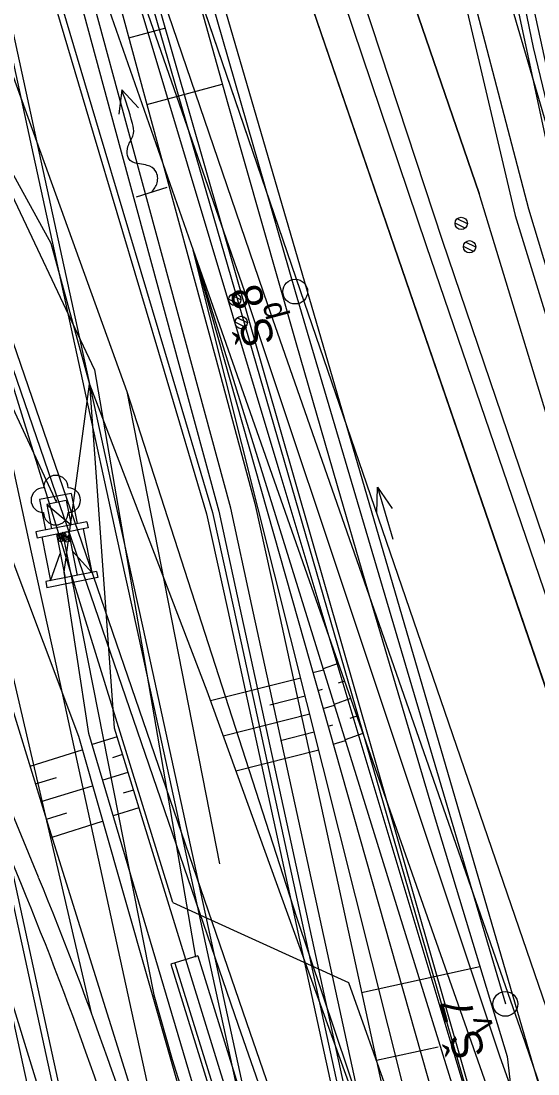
# Model space of a CAD drawing. Extents: x -439815 to -439102, y -1131353 to -1129707.
# Drawn here: x -439580.11 to -439559.22, y -1129992.98 to -1129950.45 of the extents above; entities that cross this region are included whole.
import ezdxf

# ---------------------------------------------------------------- set-up
doc = ezdxf.new("R2010")
doc.units = 0
for name, color, linetype in [('Level 1', 7, 'Continuous'), ('Level 10', 7, 'Continuous'), ('Level 11', 7, 'Continuous'), ('Level 15', 7, 'Continuous'), ('Level 18', 7, 'Continuous'), ('Level 20', 7, 'Continuous'), ('Level 24', 7, 'Continuous'), ('Level 25', 7, 'Continuous'), ('Level 36', 7, 'Continuous'), ('Level 4', 7, 'Continuous'), ('Level 42', 7, 'Continuous'), ('Level 45', 7, 'Continuous'), ('Level 47', 7, 'Continuous'), ('Level 48', 7, 'Continuous'), ('Level 49', 7, 'Continuous'), ('Level 5', 7, 'Continuous'), ('Level 50', 7, 'Continuous'), ('Level 52', 7, 'Continuous'), ('Level 57', 7, 'Continuous'), ('Level 59', 7, 'Continuous'), ('Level 61', 7, 'Continuous'), ('Level 62', 7, 'Continuous'), ('Level 63', 7, 'Continuous'), ('Level 9', 7, 'Continuous')]:
    doc.layers.add(name, color=color, linetype=linetype)

# ---------------------------------------------------------------- blocks, each defined once
blk = doc.blocks.new('LAPAC_')
at = {"layer": 'Level 1'}
for p, q in [((5, 10.49), (5, -10.5)), ((5, 10.49), (7.51, 10.49)), ((7.51, 10.49), (7.53, -10.5)), ((25.5, 10.47), (28, 10.48)), ((25.5, 10.47), (25.5, -10.5)), ((28, 10.48), (28.01, -10.48)), ((-7.5, 6.5), (4.99, 6.51)), ((-7.5, 6.5), (-7.49, -6.51)), ((7.51, 8.5), (25.51, 8.49)), ((25.49, 8.48), (15.5, 2.5)), ((-4.98, 4), (-5, -4)), ((-5, -4), (5, 4)), ((-4.98, 4), (5.01, 4)), ((7.51, 2.5), (25.5, 2.51)), ((-5, -4), (4.99, -4)), ((7.51, 0), (28, 0)), ((7.51, -2.49), (25.5, -2.51)), ((25.51, -8.49), (15.52, -2.5)), ((-7.49, -6.51), (4.99, -6.51)), ((7.51, -8.5), (25.51, -8.49)), ((5, -10.5), (7.53, -10.5)), ((25.5, -10.5), (28.01, -10.48))]:
    blk.add_line(p, q, dxfattribs=at)
for centre in [(8.3, 1.56), (8.3, 0.16), (8.67, -0.69), (9.89, 0.34), (10.54, 1.36), (8.76, -1.44), (9.88, -1.16)]:
    blk.add_circle(centre, 1, dxfattribs=at)

msp = doc.modelspace()

# ---------------------------------------------------------------- linework, layer by layer
at = {"layer": 'Level 10'}
for p, q in [((-439567.29, -1129976.404), (-439567.902, -1129976.618)), ((-439568.312, -1129976.77), (-439567.89, -1129976.65)), ((-439568.806, -1129976.996), (-439572.45, -1129977.912)), ((-439567.04, -1129977.112), (-439567.294, -1129977.2)), ((-439568.622, -1129977.724), (-439570.052, -1129978.084)), ((-439568.106, -1129977.492), (-439567.93, -1129977.44)), ((-439567.902, -1129978.212), (-439567.446, -1129978.084)), ((-439566.79, -1129977.82), (-439567.456, -1129978.052)), ((-439568.44, -1129978.45), (-439571.938, -1129979.33)), ((-439566.542, -1129978.526), (-439566.818, -1129978.624)), ((-439567.698, -1129978.934), (-439567.508, -1129978.88)), ((-439576.226, -1129979.364), (-439577.232, -1129979.674)), ((-439568.258, -1129979.178), (-439569.626, -1129979.522)), ((-439566.294, -1129979.234), (-439567.01, -1129979.486)), ((-439579.738, -1129980.544), (-439577.63, -1129979.894)), ((-439568.074, -1129979.906), (-439571.424, -1129980.748)), ((-439567.494, -1129979.656), (-439567, -1129979.516)), ((-439576.006, -1129980.082), (-439576.41, -1129980.206)), ((-439579.516, -1129981.262), (-439578.678, -1129981.002)), ((-439575.784, -1129980.798), (-439576.806, -1129981.112)), ((-439579.294, -1129981.978), (-439577.218, -1129981.338)), ((-439575.564, -1129981.514), (-439575.974, -1129981.642)), ((-439579.074, -1129982.694), (-439578.25, -1129982.438)), ((-439575.342, -1129982.23), (-439576.378, -1129982.55)), ((-439578.852, -1129983.41), (-439576.81, -1129982.77))]:
    msp.add_line(p, q, dxfattribs=at)
msp.add_lwpolyline([(-439606.718, -1129878.884), (-439599.16, -1129893.286), (-439591.48, -1129910.122), (-439589.662, -1129921.096), (-439588.348, -1129928.69), (-439584.254, -1129940.826), (-439581.56, -1129949.574), (-439575.832, -1129965.416), (-439572.088, -1129984.488)], dxfattribs=at)
at = {"layer": 'Level 11'}
for points in [[(-439631.45, -1129824.71), (-439623.296, -1129852.5), (-439607.812, -1129902.52), (-439594.486, -1129945.364), (-439588.77, -1129963.69), (-439582.318, -1129984.12), (-439576.384, -1130003.39), (-439571.028, -1130020.78), (-439569.524, -1130025.24)], [(-439572.89, -1130002.436), (-439578.954, -1129983.086), (-439585.23, -1129962.72)]]:
    msp.add_lwpolyline(points, dxfattribs=at)
at = {"layer": 'Level 15'}
for p, q in [((-439575.752, -1129951.124), (-439574.25, -1129950.717)), ((-439575.021, -1129953.819), (-439571.975, -1129952.994)), ((-439562.158, -1129958.81), (-439562.568, -1129958.608)), ((-439562.072, -1129958.642), (-439562.488, -1129958.44)), ((-439561.736, -1129959.588), (-439562.152, -1129959.384)), ((-439561.82, -1129959.754), (-439562.232, -1129959.554)), ((-439571.222, -1129961.716), (-439571.638, -1129961.514)), ((-439571.308, -1129961.884), (-439571.718, -1129961.682)), ((-439570.96, -1129962.646), (-439571.376, -1129962.444)), ((-439571.044, -1129962.814), (-439571.456, -1129962.612)), ((-439566.346, -1129989.687), (-439561.562, -1129988.644)), ((-439565.749, -1129992.426), (-439563.249, -1129991.881))]:
    msp.add_line(p, q, dxfattribs=at)
for centre in [(-439562.319, -1129958.622), (-439561.982, -1129959.566), (-439571.47, -1129961.695), (-439571.207, -1129962.626)]:
    msp.add_circle(centre, 0.25, dxfattribs=at)
at = {"layer": 'Level 18'}
msp.add_lwpolyline([(-439631.86, -1129744.036), (-439633.367, -1129748.063), (-439622.927, -1129795.938), (-439612.487, -1129843.813), (-439602.046, -1129891.688), (-439593.233, -1129932.103), (-439588.758, -1129952.621), (-439584.284, -1129973.139), (-439579.81, -1129993.657), (-439575.335, -1130014.174), (-439566.386, -1130055.21)], dxfattribs=at)
at = {"layer": 'Level 20'}
for points in [[(-439447.35, -1130302.89), (-439457.16, -1130275.562), (-439478.968, -1130210.544), (-439490.24, -1130177.636), (-439501.606, -1130144.528), (-439511.068, -1130116.958), (-439519.726, -1130091.71), (-439522.682, -1130083.14), (-439529.956, -1130061.912), (-439534.024, -1130050.036), (-439543.72, -1130021.718), (-439554.45, -1129990.362), (-439564.874, -1129960.014), (-439575.322, -1129929.52)], [(-439450.914, -1130305.246), (-439460.972, -1130277.082), (-439482.918, -1130211.888), (-439494.254, -1130178.768), (-439505.592, -1130145.672), (-439514.996, -1130118.198), (-439526.684, -1130084.16), (-439534.114, -1130062.498), (-439537.924, -1130051.384), (-439547.688, -1130022.904), (-439558.398, -1129991.686), (-439568.82, -1129961.348), (-439579.29, -1129930.716)]]:
    msp.add_lwpolyline(points, dxfattribs=at)
at = {"layer": 'Level 24'}
msp.add_line((-439580.77, -1129965.363), (-439578.671, -1129969.901), dxfattribs=at)
at = {"layer": 'Level 36'}
for p, q in [((-439573.97, -1129986.06), (-439607.88, -1129876.57)), ((-439573.27, -1129886.24), (-439556.9, -1129961.42)), ((-439573.97, -1129986.06), (-439572.59, -1129986.69)), ((-439572.59, -1129986.69), (-439566.87, -1129989.29)), ((-439566.87, -1129989.29), (-439527.69, -1130099.7))]:
    msp.add_line(p, q, dxfattribs=at)
at = {"layer": 'Level 4'}
for points in [[(-439452.672, -1130307.618), (-439463.136, -1130278.208), (-439473.444, -1130247.422), (-439485.028, -1130212.568), (-439496.122, -1130179.246), (-439507.47, -1130146.338), (-439516.97, -1130118.814), (-439528.894, -1130083.662), (-439539.69, -1130052.08), (-439549.11, -1130024.836), (-439560.748, -1129992.304), (-439571.06, -1129961.386), (-439580.88, -1129933.18), (-439592.05, -1129899.854), (-439602.118, -1129867.674), (-439610.398, -1129839.158), (-439617.774, -1129811.206), (-439624.664, -1129780.682), (-439629.998, -1129755.268)], [(-439452.072, -1130307.172), (-439462.466, -1130278.094), (-439473.084, -1130245.544), (-439484.196, -1130212.422), (-439495.494, -1130179.146), (-439506.764, -1130146.202), (-439516.426, -1130118.702), (-439528.244, -1130083.58), (-439539.098, -1130051.84), (-439548.434, -1130024.652), (-439559.722, -1129991.734), (-439570.14, -1129961.918), (-439579.974, -1129933.094), (-439590.708, -1129900.372), (-439601.098, -1129867.326), (-439609.248, -1129839.62), (-439616.746, -1129811.082), (-439623.958, -1129780.222), (-439629.3, -1129755.206)], [(-439446.102, -1130302.732), (-439455.792, -1130275.852), (-439466.676, -1130243.236), (-439477.16, -1130212.046), (-439488.92, -1130177.274), (-439500.288, -1130144.12), (-439509.364, -1130116.456), (-439521.914, -1130080.954), (-439532.724, -1130049.53), (-439541.918, -1130022.91), (-439553.308, -1129989.992), (-439563.72, -1129959.534), (-439573.732, -1129929.866), (-439583.77, -1129899.796), (-439594.604, -1129865.112), (-439602.866, -1129836.696), (-439610.248, -1129808.686), (-439617.812, -1129776.402), (-439620.902, -1129760.638), (-439620.878, -1129760.216)], [(-439445.336, -1130302.16), (-439455.084, -1130275.71), (-439466.188, -1130243.062), (-439488.304, -1130177.006), (-439499.622, -1130143.812), (-439508.924, -1130116.27), (-439521.236, -1130080.8), (-439532.228, -1130049.328), (-439540.848, -1130022.744), (-439552.746, -1129989.722), (-439563.07, -1129959.314), (-439572.718, -1129930.014), (-439582.84, -1129899.55), (-439593.798, -1129865.15), (-439602.014, -1129836.3), (-439609.444, -1129808.656), (-439617.162, -1129776.376), (-439620.256, -1129761.088), (-439620.404, -1129760.148)]]:
    msp.add_lwpolyline(points, dxfattribs=at)
at = {"layer": 'Level 42'}
for points in [[(-439571.26, -1129941.374), (-439564.874, -1129960.014), (-439554.45, -1129990.362), (-439543.72, -1130021.718), (-439534.024, -1130050.036), (-439529.956, -1130061.912), (-439522.682, -1130083.14), (-439519.726, -1130091.71), (-439511.068, -1130116.958), (-439501.606, -1130144.528), (-439490.24, -1130177.636), (-439478.968, -1130210.544), (-439457.16, -1130275.562), (-439447.35, -1130302.89), (-439445.462, -1130308.388), (-439445.064, -1130309.558), (-439434.464, -1130340.548), (-439423.826, -1130371.538), (-439413.424, -1130401.962), (-439403.314, -1130431.488), (-439395.105, -1130455.427)], [(-439399.158, -1130456.267), (-439407.226, -1130432.678), (-439417.232, -1130403.478), (-439427.682, -1130373.028), (-439438.464, -1130341.588), (-439448.942, -1130311.012), (-439450.914, -1130305.246), (-439460.972, -1130277.082), (-439482.918, -1130211.888), (-439494.254, -1130178.768), (-439505.592, -1130145.672), (-439514.996, -1130118.198), (-439526.684, -1130084.16), (-439534.114, -1130062.498), (-439537.924, -1130051.384), (-439547.688, -1130022.904), (-439558.398, -1129991.686), (-439568.82, -1129961.348), (-439575.094, -1129942.992)]]:
    msp.add_lwpolyline(points, dxfattribs=at)
at = {"layer": 'Level 45'}
msp.add_lwpolyline([(-439543.649, -1130001.679), (-439556.991, -1129961.508), (-439559.4, -1129951.517), (-439562.492, -1129936.521)], dxfattribs=at)
at = {"layer": 'Level 47'}
for p, q in [((-439577.344, -1129932.554), (-439569.026, -1129961.378)), ((-439569.026, -1129961.378), (-439560.537, -1129990.152))]:
    msp.add_line(p, q, dxfattribs=at)
for centre in [(-439569.026, -1129961.378), (-439560.537, -1129990.152)]:
    msp.add_circle(centre, 0.5, dxfattribs=at)
at = {"layer": 'Level 48'}
for p, q in [((-439576.032, -1129953.234), (-439576.158, -1129954.215)), ((-439576.032, -1129953.234), (-439575.363, -1129953.959)), ((-439574.215, -1129957.17), (-439575.456, -1129957.563))]:
    msp.add_line(p, q, dxfattribs=at)
msp.add_spline([(-439574.837, -1129957.371), (-439574.606, -1129956.979), (-439574.665, -1129956.52), (-439575.005, -1129956.278), (-439575.324, -1129956.22), (-439575.696, -1129956.082), (-439575.816, -1129955.803), (-439575.756, -1129955.432), (-439575.561, -1129954.993), (-439575.603, -1129954.592), (-439576.032, -1129953.234)], degree=3, dxfattribs=at)
at = {"layer": 'Level 49'}
msp.add_line((-439565.704, -1129969.274), (-439565.081, -1129971.38), dxfattribs=at)
msp.add_lwpolyline([(-439565.732, -1129970.325), (-439565.704, -1129969.274), (-439565.109, -1129970.141)], dxfattribs=at)
at = {"layer": 'Level 5'}
for points in [[(-439524.128, -1130104.684), (-439542.36, -1130053.899), (-439560.483, -1129998.857), (-439575.708, -1129945.714), (-439590.289, -1129890.237), (-439603.222, -1129834.191), (-439614.978, -1129781.165), (-439626.657, -1129727.981), (-439631.05, -1129707.012)], [(-439587.117, -1129895.735), (-439584.686, -1129905.44), (-439582.203, -1129915.134), (-439580.689, -1129920.945), (-439579.669, -1129924.816), (-439577.082, -1129934.487), (-439574.443, -1129944.147), (-439571.752, -1129953.795), (-439569.009, -1129963.432), (-439567.338, -1129969.208), (-439566.214, -1129973.057), (-439563.366, -1129982.671), (-439560.466, -1129992.274), (-439559.308, -1130002.256), (-439558.201, -1130012.25), (-439555.572, -1130021.911), (-439553.075, -1130031.602), (-439552.175, -1130035.027)], [(-439590.756, -1129896.529), (-439588.625, -1129906.299), (-439586.494, -1129916.07), (-439585.216, -1129921.932), (-439584.168, -1129925.797), (-439581.549, -1129935.461), (-439578.93, -1129945.125), (-439576.311, -1129954.789), (-439573.692, -1129964.453), (-439572.12, -1129970.251), (-439571.268, -1129974.159), (-439569.137, -1129983.93), (-439567.006, -1129993.7), (-439564.876, -1130003.47), (-439562.745, -1130013.241), (-439560.614, -1130023.011), (-439558.484, -1130032.781), (-439556.976, -1130039.694), (-439556.353, -1130042.552), (-439554.222, -1130052.322), (-439552.092, -1130062.093), (-439551.741, -1130063.699)], [(-439556.38, -1130040.02), (-439557.995, -1130032.675), (-439560.126, -1130022.905), (-439562.257, -1130013.134), (-439564.387, -1130003.364), (-439566.518, -1129993.593), (-439568.649, -1129983.823), (-439570.779, -1129974.053), (-439571.634, -1129970.132), (-439573.209, -1129964.322), (-439575.828, -1129954.658), (-439578.447, -1129944.994), (-439581.067, -1129935.33), (-439583.686, -1129925.667), (-439584.73, -1129921.813), (-439586.006, -1129915.963), (-439588.136, -1129906.193), (-439590.267, -1129896.422)], [(-439589.29, -1129896.209), (-439587.159, -1129905.98), (-439585.029, -1129915.75), (-439583.75, -1129921.612), (-439582.703, -1129925.478), (-439580.084, -1129935.142), (-439577.464, -1129944.805), (-439574.845, -1129954.469), (-439572.226, -1129964.133), (-439570.654, -1129969.931), (-439569.802, -1129973.84), (-439567.672, -1129983.61), (-439565.541, -1129993.38), (-439563.41, -1130003.151), (-439561.28, -1130012.921), (-439559.149, -1130022.691), (-439557.018, -1130032.462), (-439555.511, -1130039.375), (-439554.888, -1130042.232), (-439552.757, -1130052.003), (-439550.626, -1130061.773), (-439548.496, -1130071.543), (-439547.692, -1130075.226)], [(-439592.465, -1129896.902), (-439590.335, -1129906.672), (-439588.204, -1129916.442), (-439586.926, -1129922.305), (-439586.073, -1129926.213), (-439583.943, -1129935.983), (-439581.812, -1129945.754), (-439579.682, -1129955.524), (-439577.551, -1129965.294), (-439576.272, -1129971.157), (-439575.42, -1129975.065), (-439573.29, -1129984.835), (-439571.159, -1129994.605), (-439569.028, -1130004.376), (-439566.898, -1130014.146), (-439564.767, -1130023.917), (-439562.636, -1130033.687), (-439561.129, -1130040.6)], [(-439592.221, -1129896.848), (-439590.091, -1129906.619), (-439587.96, -1129916.389), (-439586.682, -1129922.251), (-439585.829, -1129926.16), (-439583.699, -1129935.93), (-439581.568, -1129945.7), (-439579.437, -1129955.471), (-439577.307, -1129965.241), (-439576.028, -1129971.103), (-439575.176, -1129975.011), (-439573.045, -1129984.782), (-439570.915, -1129994.552), (-439568.784, -1130004.323), (-439566.653, -1130014.093), (-439564.523, -1130023.863), (-439562.392, -1130033.634), (-439560.884, -1130040.547)], [(-439595.885, -1129897.647), (-439593.754, -1129907.418), (-439591.624, -1129917.188), (-439590.345, -1129923.05), (-439589.493, -1129926.959), (-439587.362, -1129936.729), (-439585.232, -1129946.499), (-439583.101, -1129956.27), (-439580.97, -1129966.04), (-439579.692, -1129971.902), (-439578.84, -1129975.81), (-439576.709, -1129985.581), (-439574.578, -1129995.351), (-439572.448, -1130005.122), (-439570.317, -1130014.892), (-439568.186, -1130024.662), (-439566.056, -1130034.433), (-439564.548, -1130041.346)], [(-439599.549, -1129898.446), (-439597.418, -1129908.217), (-439595.288, -1129917.987), (-439594.009, -1129923.849), (-439593.157, -1129927.758), (-439591.026, -1129937.528), (-439588.896, -1129947.298), (-439586.765, -1129957.069), (-439584.634, -1129966.839), (-439583.356, -1129972.701), (-439582.504, -1129976.609), (-439580.373, -1129986.38), (-439578.242, -1129996.15), (-439576.112, -1130005.921), (-439573.981, -1130015.691), (-439571.85, -1130025.461), (-439569.72, -1130035.232), (-439568.212, -1130042.145)], [(-439599.305, -1129898.393), (-439597.174, -1129908.164), (-439595.043, -1129917.934), (-439593.765, -1129923.796), (-439592.913, -1129927.704), (-439590.782, -1129937.475), (-439588.651, -1129947.245), (-439586.521, -1129957.015), (-439584.39, -1129966.786), (-439583.112, -1129972.648), (-439582.259, -1129976.556), (-439580.129, -1129986.327), (-439577.998, -1129996.097), (-439575.867, -1130005.867), (-439573.737, -1130015.638), (-439571.606, -1130025.408), (-439569.475, -1130035.178), (-439567.968, -1130042.091)], [(-439587.96, -1129916.389), (-439586.682, -1129922.251), (-439585.536, -1129926.096), (-439582.673, -1129935.706), (-439579.809, -1129945.317), (-439576.946, -1129954.927), (-439574.082, -1129964.538), (-439572.364, -1129970.304), (-439571.512, -1129974.212), (-439569.381, -1129983.983), (-439567.251, -1129993.753), (-439565.12, -1130003.524), (-439562.989, -1130013.294), (-439560.859, -1130023.064), (-439558.728, -1130032.835), (-439557.22, -1130039.748), (-439556.597, -1130042.605), (-439554.467, -1130052.375), (-439552.336, -1130062.146), (-439550.379, -1130071.121)], [(-439586.934, -1129922.311), (-439586.926, -1129922.305), (-439585.78, -1129926.149), (-439582.917, -1129935.76), (-439580.053, -1129945.37), (-439577.19, -1129954.981), (-439574.327, -1129964.591), (-439572.609, -1129970.358), (-439571.756, -1129974.266), (-439569.626, -1129984.036), (-439567.495, -1129993.806), (-439565.364, -1130003.577), (-439563.234, -1130013.347), (-439561.103, -1130023.118), (-439558.972, -1130032.888), (-439557.465, -1130039.801), (-439556.842, -1130042.658), (-439554.711, -1130052.429), (-439552.58, -1130062.199), (-439551.985, -1130064.928)]]:
    msp.add_lwpolyline(points, dxfattribs=at)
at = {"layer": 'Level 50'}
msp.add_line((-439578.732, -1129969.804), (-439578.66, -1129969.804), dxfattribs=at)
for centre, start, end in [((-439578.701, -1129969.303), 0, 180), ((-439579.201, -1129969.803), 90, 270), ((-439578.201, -1129969.803), 270, 90), ((-439578.701, -1129970.303), 180, 0)]:
    msp.add_arc(centre, 0.5, start, end, dxfattribs=at)
at = {"layer": 'Level 52'}
for p, q in [((-439583.644, -1129950.788), (-439577.136, -1129964.538)), ((-439577.136, -1129964.538), (-439573.056, -1129988.268)), ((-439582.952, -1129966.168), (-439577.266, -1129990.506)), ((-439579.398, -1129985.038), (-439584.406, -1129972.9)), ((-439580.09, -1129985.324), (-439585.118, -1129973.142)), ((-439578.032, -1129973.138), (-439574.742, -1129989.788)), ((-439572.956, -1129988.212), (-439574.054, -1129988.552))]:
    msp.add_line(p, q, dxfattribs=at)
for points in [[(-439572.956, -1129988.212), (-439566.758, -1130008.234)], [(-439574.054, -1129988.552), (-439567.864, -1130008.55)], [(-439573.89, -1129988.502), (-439570.934, -1129998.056)], [(-439574.742, -1129989.788), (-439574, -1129992.396), (-439568.824, -1130008.828)]]:
    msp.add_lwpolyline(points, dxfattribs=at)
for radius in [150.5, 151.25]:
    msp.add_arc((-439719.223, -1130042.705), radius, 16.09885, 22.41188, dxfattribs=at)
at = {"layer": 'Level 57'}
for p, q in [((-439615.997, -1129861.04), (-439571.326, -1129991.012)), ((-439571.326, -1129991.012), (-439532.649, -1130102.737))]:
    msp.add_line(p, q, dxfattribs=at)
at = {"layer": 'Level 59'}
for p, q in [((-439615.666, -1129860.926), (-439570.995, -1129990.899)), ((-439570.995, -1129990.898), (-439532.318, -1130102.623))]:
    msp.add_line(p, q, dxfattribs=at)
msp.add_lwpolyline([(-439565.323, -1129925.255), (-439558.917, -1129955.176), (-439557.476, -1129961.905), (-439549.066, -1129985.001)], dxfattribs=at)
at = {"layer": 'Level 61'}
for p, q in [((-439547.146, -1129994.737), (-439562.474, -1129942.35)), ((-439573.227, -1129945.323), (-439557.81, -1129998.142))]:
    msp.add_line(p, q, dxfattribs=at)
at = {"layer": 'Level 62'}
msp.add_line((-439560.603, -1129998.786), (-439575.875, -1129946.07), dxfattribs=at)
at = {"layer": 'Level 63'}
msp.add_lwpolyline([(-439559.899, -1130001.173), (-439569.713, -1129968.453), (-439577.958, -1129940.931), (-439581.389, -1129927.721), (-439587.866, -1129899.446), (-439590.167, -1129890.323), (-439596.266, -1129862.915), (-439602.978, -1129834.556), (-439615.089, -1129778.896), (-439619.056, -1129758.708), (-439624.106, -1129738.276), (-439628.163, -1129719.403), (-439630.545, -1129707.012)], dxfattribs=at)
at = {"layer": 'Level 9'}
for p, q in [((-439573.156, -1129959.7), (-439550.138, -1130025.226)), ((-439578.362, -1129972.718), (-439577.34, -1129965.12))]:
    msp.add_line(p, q, dxfattribs=at)
for points in [[(-439615.016, -1129861.902), (-439609.016, -1129872.388), (-439598.672, -1129902.048), (-439593.08, -1129922.412), (-439591.246, -1129928.438), (-439589.858, -1129932.272), (-439590.514, -1129935.246), (-439587.63, -1129940.776), (-439586.318, -1129945.922), (-439578.898, -1129959.416), (-439577.34, -1129965.12), (-439572.6, -1129977.504), (-439565.568, -1129996.93)], [(-439561.59, -1129957.412), (-439568.484, -1129937.326), (-439572.75, -1129923.344)], [(-439583.996, -1129927.66), (-439580.782, -1129937.88), (-439573.156, -1129959.7)], [(-439565.696, -1129934.664), (-439560.14, -1129958.304), (-439549.714, -1129992.178), (-439541.66, -1130014.164), (-439534.13, -1130036.788), (-439529.434, -1130049.122)], [(-439529.434, -1130049.122), (-439533.642, -1130036.612), (-439541.214, -1130013.966), (-439549.356, -1129991.93), (-439559.582, -1129958.054), (-439565.696, -1129934.664)], [(-439568.484, -1129937.326), (-439561.59, -1129957.412)], [(-439588.27, -1129946.636), (-439583.488, -1129962.072), (-439583.98, -1129962.938), (-439582.788, -1129966.044), (-439577.788, -1129979.34), (-439572.16, -1129999.082), (-439566.194, -1130018.824), (-439554.92, -1130053.378)], [(-439539.78, -1130021.546), (-439551.914, -1129989.212), (-439561.59, -1129957.412)], [(-439539.976, -1130066.112), (-439543.636, -1130055.94), (-439548.718, -1130040.922), (-439555.81, -1130018.284), (-439563.966, -1129996.25), (-439573.156, -1129959.7)], [(-439573.156, -1129959.7), (-439562.928, -1129995.746), (-439555.81, -1130018.284)], [(-439573.156, -1129959.7), (-439561.968, -1129995.718), (-439554.008, -1130017.84), (-439547.068, -1130040.406), (-439541.34, -1130055.714), (-439538.356, -1130063.796)], [(-439577.34, -1129965.12), (-439576.34, -1129978.998), (-439570.26, -1129998.734), (-439564.65, -1130018.494)], [(-439575.832, -1129965.416), (-439568.974, -1129986.65), (-439562.208, -1130006.75), (-439555.4, -1130027.656), (-439549.7, -1130045.104), (-439543.224, -1130064.878), (-439534.136, -1130092.886), (-439531.324, -1130101.162), (-439529.482, -1130100.572)], [(-439554.92, -1130053.378), (-439565.49, -1130018.736), (-439571.516, -1129998.944), (-439577.362, -1129979.234), (-439578.362, -1129972.718)]]:
    msp.add_lwpolyline(points, dxfattribs=at)

# ---------------------------------------------------------------- block references
at = {"layer": 'Level 25', "xscale": 0.1, "yscale": 0.10000000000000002, "rotation": -78.79788058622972}
msp.add_blockref('LAPAC_', (-439578.575, -1129970.389), dxfattribs=at)

# ---------------------------------------------------------------- texts
at = {"layer": 'Level 49'}
for s, height, p in [('Š 8', 1.25, (-439569.832, -1129963.418)), ('p', 0.938, (-439569.48, -1129962.398)), ('Š 7', 1.25, (-439561.343, -1129992.191)), ('v', 0.937, (-439560.991, -1129991.172))]:
    msp.add_text(s, height=height, rotation=104.8992, dxfattribs=at).set_placement(p)

doc.saveas('drawing.dxf')
